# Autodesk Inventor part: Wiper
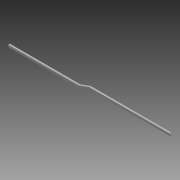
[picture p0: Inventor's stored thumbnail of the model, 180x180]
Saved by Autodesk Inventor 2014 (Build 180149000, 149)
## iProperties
Created: 2006-03
Part Number: Wiper
Document SubType Name: Modeling
Designer: debonom
Material: Stainless Steel, 440C
Mass: 28.0148 g
Surface Area: 42.4106 cm^2
Volume: 3.61481 cm^3
Density: 7.75 g/cm^3
Appearance: Steel
Author: debonom
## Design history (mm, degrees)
sketch "Sketch1"
  geometry: L1 (-1.5, 2)-(1.5, 2); L2 (1.5, 2)-(1.5, -2); L3 (1.5, -2)-(-1.5, -2); L4 (-1.5, -2)-(-1.5, 2); L5 (-1.5, 2)-(1.5, -2); 2 further points
  constraints: 10 end point, 2 parallel, 1 coincident, 1 horizontal, 1 midpoint, 1 perpendicular
  dimensions: "d0" = 3 distance of L1.start L1.end; "d1" = 4 distance of L3.end L1.start
sketch "Sketch2"
  geometry: L1 (0, 0)-(150, 0); L2 (150, 0)-(169.232, -7); L3 (169.232, -7)-(300, -7)
  constraints: 6 end point, 1 horizontal, 1 parallel
  dimensions: "d2" = 150 distance of L1.start L1.end; "d3" = 160 deg angle of L2 L1; "d4" = 300 horizontal distance of L3.end L1.start; "d5" = 7 distance between parallel lines of L3 L1
sweep "Sweep1" sketch "Sketch1", "Sketch2" dims "d6" = 0
fillet "Fillet1" dims "d7" = 5
workaxis "Work Axis1"
workaxis "Work Axis2"
body "Solid1"
